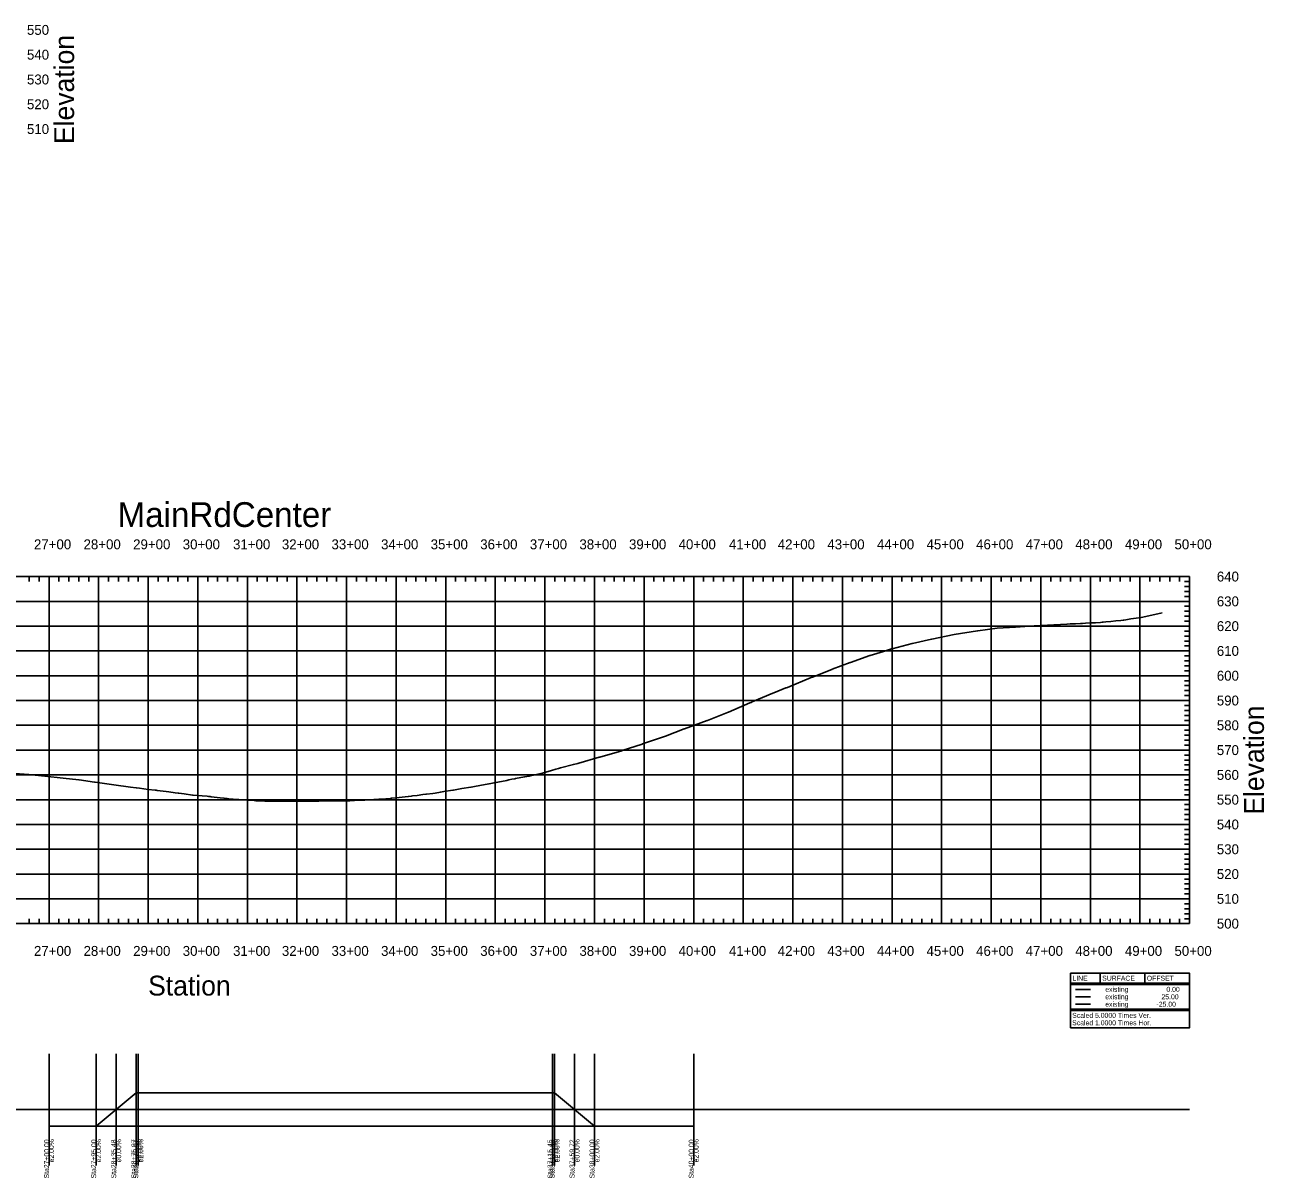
# Model space of a CAD drawing. Extents: x 708167 to 712470, y 374476 to 376945.
# Drawn here: x 709970 to 712470, y 374476 to 376803 of the extents above; entities that cross this region are included whole.
import ezdxf

# ---------------------------------------------------------------- set-up
doc = ezdxf.new("R2010")
doc.units = 0
for name, color, linetype in [('1', 7, 'Continuous'), ('54', 7, 'Continuous'), ('61', 7, 'Continuous'), ('63', 7, 'Continuous'), ('Existing', 7, 'Continuous')]:
    doc.layers.add(name, color=color, linetype=linetype)

msp = doc.modelspace()

# ---------------------------------------------------------------- linework, layer by layer
for points in [[(710019, 374581.2), (710114, 374581.2), (710195, 374648.4), (711038.5, 374648.4), (711119, 374581.2), (711319, 374581.2)], [(708319, 374614.8), (712319, 374614.8)], [(710019, 374581.2), (711319, 374581.2)]]:
    msp.add_lwpolyline(points)
at = {"layer": '54'}
for points in [[(710019, 374727.3), (710019, 374502.3)], [(710114, 374727.3), (710114, 374502.3)], [(710154.5, 374727.3), (710154.5, 374502.3)], [(710195, 374727.3), (710195, 374502.3)], [(710199, 374727.3), (710199, 374502.3)], [(711034.5, 374727.3), (711034.5, 374502.3)], [(711038.5, 374727.3), (711038.5, 374502.3)], [(711078.7, 374727.3), (711078.7, 374502.3)], [(711119, 374727.3), (711119, 374502.3)], [(711319, 374727.3), (711319, 374502.3)]]:
    msp.add_lwpolyline(points, dxfattribs=at)
at = {"layer": '61'}
for p, q in [((708319, 375689.8), (712319, 375689.8)), ((709979, 375689.8), (709979, 375679.8)), ((709999, 375689.8), (709999, 375679.8)), ((710019, 374989.8), (710019, 375689.8)), ((710039, 375689.8), (710039, 375679.8)), ((710059, 375689.8), (710059, 375679.8)), ((710079, 375689.8), (710079, 375679.8)), ((710099, 375689.8), (710099, 375679.8)), ((710119, 374989.8), (710119, 375689.8)), ((710139, 375689.8), (710139, 375679.8)), ((710159, 375689.8), (710159, 375679.8)), ((710179, 375689.8), (710179, 375679.8)), ((710199, 375689.8), (710199, 375679.8)), ((710219, 374989.8), (710219, 375689.8)), ((710239, 375689.8), (710239, 375679.8)), ((710259, 375689.8), (710259, 375679.8)), ((710279, 375689.8), (710279, 375679.8)), ((710299, 375689.8), (710299, 375679.8)), ((710319, 374989.8), (710319, 375689.8)), ((710339, 375689.8), (710339, 375679.8)), ((710359, 375689.8), (710359, 375679.8)), ((710379, 375689.8), (710379, 375679.8)), ((710399, 375689.8), (710399, 375679.8)), ((710419, 374989.8), (710419, 375689.8)), ((710439, 375689.8), (710439, 375679.8)), ((710459, 375689.8), (710459, 375679.8)), ((710479, 375689.8), (710479, 375679.8)), ((710499, 375689.8), (710499, 375679.8)), ((710519, 374989.8), (710519, 375689.8)), ((710539, 375689.8), (710539, 375679.8)), ((710559, 375689.8), (710559, 375679.8)), ((710579, 375689.8), (710579, 375679.8)), ((710599, 375689.8), (710599, 375679.8)), ((710619, 374989.8), (710619, 375689.8)), ((710639, 375689.8), (710639, 375679.8)), ((710659, 375689.8), (710659, 375679.8)), ((710679, 375689.8), (710679, 375679.8)), ((710699, 375689.8), (710699, 375679.8)), ((710719, 374989.8), (710719, 375689.8)), ((710739, 375689.8), (710739, 375679.8)), ((710759, 375689.8), (710759, 375679.8)), ((710779, 375689.8), (710779, 375679.8)), ((710799, 375689.8), (710799, 375679.8)), ((710819, 374989.8), (710819, 375689.8)), ((710839, 375689.8), (710839, 375679.8)), ((710859, 375689.8), (710859, 375679.8)), ((710879, 375689.8), (710879, 375679.8)), ((710899, 375689.8), (710899, 375679.8)), ((710919, 374989.8), (710919, 375689.8)), ((710939, 375689.8), (710939, 375679.8)), ((710959, 375689.8), (710959, 375679.8)), ((710979, 375689.8), (710979, 375679.8)), ((710999, 375689.8), (710999, 375679.8)), ((711019, 374989.8), (711019, 375689.8)), ((711039, 375689.8), (711039, 375679.8)), ((711059, 375689.8), (711059, 375679.8)), ((711079, 375689.8), (711079, 375679.8)), ((711099, 375689.8), (711099, 375679.8)), ((711119, 374989.8), (711119, 375689.8)), ((711139, 375689.8), (711139, 375679.8)), ((711159, 375689.8), (711159, 375679.8)), ((711179, 375689.8), (711179, 375679.8)), ((711199, 375689.8), (711199, 375679.8)), ((711219, 374989.8), (711219, 375689.8)), ((711239, 375689.8), (711239, 375679.8)), ((711259, 375689.8), (711259, 375679.8)), ((711279, 375689.8), (711279, 375679.8)), ((711299, 375689.8), (711299, 375679.8)), ((711319, 374989.8), (711319, 375689.8)), ((711339, 375689.8), (711339, 375679.8)), ((711359, 375689.8), (711359, 375679.8)), ((711379, 375689.8), (711379, 375679.8)), ((711399, 375689.8), (711399, 375679.8)), ((711419, 374989.8), (711419, 375689.8)), ((711439, 375689.8), (711439, 375679.8)), ((711459, 375689.8), (711459, 375679.8)), ((711479, 375689.8), (711479, 375679.8)), ((711499, 375689.8), (711499, 375679.8)), ((711519, 374989.8), (711519, 375689.8)), ((711539, 375689.8), (711539, 375679.8)), ((711559, 375689.8), (711559, 375679.8)), ((711579, 375689.8), (711579, 375679.8)), ((711599, 375689.8), (711599, 375679.8)), ((711619, 374989.8), (711619, 375689.8)), ((711639, 375689.8), (711639, 375679.8)), ((711659, 375689.8), (711659, 375679.8)), ((711679, 375689.8), (711679, 375679.8)), ((711699, 375689.8), (711699, 375679.8)), ((711719, 374989.8), (711719, 375689.8)), ((711739, 375689.8), (711739, 375679.8)), ((711759, 375689.8), (711759, 375679.8)), ((711779, 375689.8), (711779, 375679.8)), ((711799, 375689.8), (711799, 375679.8)), ((711819, 374989.8), (711819, 375689.8)), ((711839, 375689.8), (711839, 375679.8)), ((711859, 375689.8), (711859, 375679.8)), ((711879, 375689.8), (711879, 375679.8)), ((711899, 375689.8), (711899, 375679.8)), ((711919, 374989.8), (711919, 375689.8)), ((711939, 375689.8), (711939, 375679.8)), ((711959, 375689.8), (711959, 375679.8)), ((711979, 375689.8), (711979, 375679.8)), ((711999, 375689.8), (711999, 375679.8)), ((712019, 374989.8), (712019, 375689.8)), ((712039, 375689.8), (712039, 375679.8)), ((712059, 375689.8), (712059, 375679.8)), ((712079, 375689.8), (712079, 375679.8)), ((712099, 375689.8), (712099, 375679.8)), ((712119, 374989.8), (712119, 375689.8)), ((712139, 375689.8), (712139, 375679.8)), ((712159, 375689.8), (712159, 375679.8)), ((712179, 375689.8), (712179, 375679.8)), ((712199, 375689.8), (712199, 375679.8)), ((712219, 374989.8), (712219, 375689.8)), ((712239, 375689.8), (712239, 375679.8)), ((712259, 375689.8), (712259, 375679.8)), ((712279, 375689.8), (712279, 375679.8)), ((712299, 375689.8), (712299, 375679.8)), ((712319, 375679.8), (712309, 375679.8)), ((712319, 375669.8), (712309, 375669.8)), ((712319, 374989.8), (712319, 375689.8)), ((712319, 375659.8), (712309, 375659.8)), ((712319, 375649.8), (712309, 375649.8)), ((708319, 375639.8), (712319, 375639.8)), ((712319, 375629.8), (712309, 375629.8)), ((712319, 375619.8), (712309, 375619.8)), ((712319, 375609.8), (712309, 375609.8)), ((712319, 375599.8), (712309, 375599.8)), ((708319, 375589.8), (712319, 375589.8)), ((712319, 375579.8), (712309, 375579.8)), ((712319, 375569.8), (712309, 375569.8)), ((712319, 375559.8), (712309, 375559.8)), ((712319, 375549.8), (712309, 375549.8)), ((708319, 375539.8), (712319, 375539.8)), ((712319, 375529.8), (712309, 375529.8)), ((712319, 375519.8), (712309, 375519.8)), ((712319, 375509.8), (712309, 375509.8)), ((712319, 375499.8), (712309, 375499.8)), ((708319, 375489.8), (712319, 375489.8)), ((712319, 375479.8), (712309, 375479.8)), ((712319, 375469.8), (712309, 375469.8)), ((712319, 375459.8), (712309, 375459.8)), ((712319, 375449.8), (712309, 375449.8)), ((708319, 375439.8), (712319, 375439.8)), ((712319, 375429.8), (712309, 375429.8)), ((712319, 375419.8), (712309, 375419.8)), ((712319, 375409.8), (712309, 375409.8)), ((712319, 375399.8), (712309, 375399.8)), ((708319, 375389.8), (712319, 375389.8)), ((712319, 375379.8), (712309, 375379.8)), ((712319, 375369.8), (712309, 375369.8)), ((712319, 375359.8), (712309, 375359.8)), ((712319, 375349.8), (712309, 375349.8)), ((708319, 375339.8), (712319, 375339.8)), ((712319, 375329.8), (712309, 375329.8)), ((712319, 375319.8), (712309, 375319.8)), ((712319, 375309.8), (712309, 375309.8)), ((712319, 375299.8), (712309, 375299.8)), ((708319, 375289.8), (712319, 375289.8)), ((712319, 375279.8), (712309, 375279.8)), ((712319, 375269.8), (712309, 375269.8)), ((712319, 375259.8), (712309, 375259.8)), ((712319, 375249.8), (712309, 375249.8)), ((708319, 375239.8), (712319, 375239.8)), ((712319, 375229.8), (712309, 375229.8)), ((712319, 375219.8), (712309, 375219.8)), ((712319, 375209.8), (712309, 375209.8)), ((712319, 375199.8), (712309, 375199.8)), ((708319, 375189.8), (712319, 375189.8)), ((712319, 375179.8), (712309, 375179.8)), ((712319, 375169.8), (712309, 375169.8)), ((712319, 375159.8), (712309, 375159.8)), ((712319, 375149.8), (712309, 375149.8)), ((708319, 375139.8), (712319, 375139.8)), ((712319, 375129.8), (712309, 375129.8)), ((712319, 375119.8), (712309, 375119.8)), ((712319, 375109.8), (712309, 375109.8)), ((712319, 375099.8), (712309, 375099.8)), ((708319, 375089.8), (712319, 375089.8)), ((712319, 375079.8), (712309, 375079.8)), ((712319, 375069.8), (712309, 375069.8)), ((712319, 375059.8), (712309, 375059.8)), ((712319, 375049.8), (712309, 375049.8)), ((708319, 375039.8), (712319, 375039.8)), ((712319, 375029.8), (712309, 375029.8)), ((712319, 375019.8), (712309, 375019.8)), ((709979, 374989.8), (709979, 374999.8)), ((709999, 374989.8), (709999, 374999.8)), ((710039, 374989.8), (710039, 374999.8)), ((710059, 374989.8), (710059, 374999.8)), ((710079, 374989.8), (710079, 374999.8)), ((710099, 374989.8), (710099, 374999.8)), ((710139, 374989.8), (710139, 374999.8)), ((710159, 374989.8), (710159, 374999.8)), ((710179, 374989.8), (710179, 374999.8)), ((710199, 374989.8), (710199, 374999.8)), ((710239, 374989.8), (710239, 374999.8)), ((710259, 374989.8), (710259, 374999.8)), ((710279, 374989.8), (710279, 374999.8)), ((710299, 374989.8), (710299, 374999.8)), ((710339, 374989.8), (710339, 374999.8)), ((710359, 374989.8), (710359, 374999.8)), ((710379, 374989.8), (710379, 374999.8)), ((710399, 374989.8), (710399, 374999.8)), ((710439, 374989.8), (710439, 374999.8)), ((710459, 374989.8), (710459, 374999.8)), ((710479, 374989.8), (710479, 374999.8)), ((710499, 374989.8), (710499, 374999.8)), ((710539, 374989.8), (710539, 374999.8)), ((710559, 374989.8), (710559, 374999.8)), ((710579, 374989.8), (710579, 374999.8)), ((710599, 374989.8), (710599, 374999.8)), ((710639, 374989.8), (710639, 374999.8)), ((710659, 374989.8), (710659, 374999.8)), ((710679, 374989.8), (710679, 374999.8)), ((710699, 374989.8), (710699, 374999.8)), ((710739, 374989.8), (710739, 374999.8)), ((710759, 374989.8), (710759, 374999.8)), ((710779, 374989.8), (710779, 374999.8)), ((710799, 374989.8), (710799, 374999.8)), ((710839, 374989.8), (710839, 374999.8)), ((710859, 374989.8), (710859, 374999.8)), ((710879, 374989.8), (710879, 374999.8)), ((710899, 374989.8), (710899, 374999.8)), ((710939, 374989.8), (710939, 374999.8)), ((710959, 374989.8), (710959, 374999.8)), ((710979, 374989.8), (710979, 374999.8)), ((710999, 374989.8), (710999, 374999.8)), ((711039, 374989.8), (711039, 374999.8)), ((711059, 374989.8), (711059, 374999.8)), ((711079, 374989.8), (711079, 374999.8)), ((711099, 374989.8), (711099, 374999.8)), ((711139, 374989.8), (711139, 374999.8)), ((711159, 374989.8), (711159, 374999.8)), ((711179, 374989.8), (711179, 374999.8)), ((711199, 374989.8), (711199, 374999.8)), ((711239, 374989.8), (711239, 374999.8)), ((711259, 374989.8), (711259, 374999.8)), ((711279, 374989.8), (711279, 374999.8)), ((711299, 374989.8), (711299, 374999.8)), ((711339, 374989.8), (711339, 374999.8)), ((711359, 374989.8), (711359, 374999.8)), ((711379, 374989.8), (711379, 374999.8)), ((711399, 374989.8), (711399, 374999.8)), ((711439, 374989.8), (711439, 374999.8)), ((711459, 374989.8), (711459, 374999.8)), ((711479, 374989.8), (711479, 374999.8)), ((711499, 374989.8), (711499, 374999.8)), ((711539, 374989.8), (711539, 374999.8)), ((711559, 374989.8), (711559, 374999.8)), ((711579, 374989.8), (711579, 374999.8)), ((711599, 374989.8), (711599, 374999.8)), ((711639, 374989.8), (711639, 374999.8)), ((711659, 374989.8), (711659, 374999.8)), ((711679, 374989.8), (711679, 374999.8)), ((711699, 374989.8), (711699, 374999.8)), ((711739, 374989.8), (711739, 374999.8)), ((711759, 374989.8), (711759, 374999.8)), ((711779, 374989.8), (711779, 374999.8)), ((711799, 374989.8), (711799, 374999.8)), ((711839, 374989.8), (711839, 374999.8)), ((711859, 374989.8), (711859, 374999.8)), ((711879, 374989.8), (711879, 374999.8)), ((711899, 374989.8), (711899, 374999.8)), ((711939, 374989.8), (711939, 374999.8)), ((711959, 374989.8), (711959, 374999.8)), ((711979, 374989.8), (711979, 374999.8)), ((711999, 374989.8), (711999, 374999.8)), ((712039, 374989.8), (712039, 374999.8)), ((712059, 374989.8), (712059, 374999.8)), ((712079, 374989.8), (712079, 374999.8)), ((712099, 374989.8), (712099, 374999.8)), ((712139, 374989.8), (712139, 374999.8)), ((712159, 374989.8), (712159, 374999.8)), ((712179, 374989.8), (712179, 374999.8)), ((712199, 374989.8), (712199, 374999.8)), ((712239, 374989.8), (712239, 374999.8)), ((712259, 374989.8), (712259, 374999.8)), ((712279, 374989.8), (712279, 374999.8)), ((712299, 374989.8), (712299, 374999.8)), ((712319, 375009.8), (712309, 375009.8)), ((712319, 374999.8), (712309, 374999.8)), ((708319, 374989.8), (712319, 374989.8)), ((712079, 374869.8), (712319, 374869.8)), ((712139, 374889.8), (712139, 374869.8)), ((712229, 374889.8), (712229, 374869.8)), ((712079, 374867.3), (712319, 374867.3)), ((712079, 374817.3), (712319, 374817.3)), ((712079, 374814.8), (712319, 374814.8))]:
    msp.add_line(p, q, dxfattribs=at)
msp.add_lwpolyline([(712079, 374889.8), (712319, 374889.8), (712319, 374779.8), (712079, 374779.8)], close=True, dxfattribs=at)
at = {"layer": '63'}
for p, q in [((712089, 374842.3), (712119, 374842.3)), ((712089, 374827.3), (712119, 374827.3))]:
    msp.add_line(p, q, dxfattribs=at)
at = {"layer": 'Existing'}
msp.add_line((712089, 374857.3), (712119, 374857.3), dxfattribs=at)
msp.add_lwpolyline([(709941.7, 375293.2), (709977.7, 375290.3), (709978.4, 375290.3), (710010.5, 375287.5), (710010.8, 375287.4), (710047.4, 375283.3), (710047.5, 375283.3), (710079.1, 375279.5), (710079.5, 375279.5), (710111, 375275.3), (710112, 375275.2), (710149.4, 375269.9), (710149.5, 375269.9), (710149.6, 375269.9), (710183.1, 375265.3), (710194.5, 375263.8), (710195.3, 375263.7), (710201.2, 375262.9), (710219.2, 375260.6), (710233, 375258.9), (710233.5, 375258.8), (710234, 375258.8), (710235, 375258.7), (710237.3, 375258.4), (710255.4, 375256.1), (710260.9, 375255.4), (710273.4, 375253.7), (710279.4, 375253), (710280.4, 375252.8), (710280.5, 375253), (710280.9, 375252.9), (710291.5, 375251.5), (710308.6, 375249.2), (710309.6, 375249.1), (710309.8, 375249.1), (710327.6, 375247.5), (710338.1, 375246.6), (710340.3, 375246.4), (710340.4, 375246.4), (710344.2, 375245.9), (710345.7, 375245.8), (710363.8, 375243.7), (710371.6, 375242.8), (710372.1, 375242.8), (710378.5, 375242.2), (710381.8, 375241.8), (710399.9, 375240), (710401.2, 375239.9), (710402.4, 375239.8), (710418, 375238.9), (710432.4, 375238), (710432.7, 375238), (710436, 375237.8), (710454.1, 375237), (710462.3, 375236.7), (710463.2, 375236.6), (710472.2, 375236.6), (710490.2, 375236.6), (710496.4, 375236.6), (710497.6, 375236.6), (710508.3, 375236.7), (710526.4, 375236.8), (710528.9, 375236.9), (710530.1, 375236.9), (710544.4, 375236.9), (710562.1, 375237), (710562.5, 375237), (710562.9, 375237), (710580.6, 375237.2), (710590.2, 375237.3), (710590.8, 375237.3), (710598.6, 375237.4), (710616.7, 375237.4), (710622.2, 375237.5), (710624, 375237.5), (710625.8, 375237.6), (710634.8, 375238), (710652.8, 375238.8), (710655.7, 375238.9), (710655.9, 375239), (710670.9, 375239.8), (710674, 375239.9), (710678.6, 375240.3), (710680.9, 375240.4), (710683.8, 375240.6), (710689, 375241), (710707.1, 375242.5), (710707.8, 375242.5), (710709.4, 375242.6), (710725.1, 375244.3), (710743.2, 375246.3), (710744.2, 375246.5), (710749.6, 375246.8), (710751.8, 375247.3), (710761.3, 375248.2), (710761.4, 375248.2), (710772.8, 375250.1), (710779, 375250.6), (710779.3, 375250.7), (710780.5, 375251), (710793.1, 375252.2), (710797.4, 375252.9), (710798, 375253), (710808.3, 375255.1), (710815.5, 375256.1), (710833.5, 375258.9), (710834.7, 375259), (710838.3, 375259.7), (710844.9, 375260.9), (710851.6, 375262.1), (710869.7, 375265.1), (710870, 375265.2), (710870.3, 375265.2), (710876.7, 375266.3), (710887.7, 375268.3), (710905.8, 375271.6), (710906.8, 375271.8), (710913, 375273), (710916.2, 375273.6), (710916.3, 375273.7), (710917.1, 375274), (710923.9, 375275.3), (710941.9, 375278.8), (710946.3, 375279.7), (710952, 375280.9), (710958, 375282), (710958.6, 375282), (710960, 375282.3), (710978.1, 375285.7), (710987, 375287.5), (710993.8, 375289), (710996.1, 375289.3), (710998.5, 375289.7), (711014.2, 375293.4), (711018.1, 375294.3), (711018.7, 375294.3), (711019.3, 375294.4), (711020.6, 375295), (711032.3, 375298.8), (711041.2, 375301.6), (711046.1, 375302.9), (711050.3, 375304), (711076.5, 375310.8), (711085.1, 375313), (711087.2, 375313.6), (711128.4, 375325.3), (711129, 375325.5), (711129, 375325.5), (711129.7, 375325.7), (711173.9, 375338.6), (711174.5, 375338.8), (711175, 375339), (711215, 375351.8), (711215.1, 375351.8), (711215.9, 375352.1), (711262, 375368.2), (711300, 375382.6), (711300.6, 375382.8), (711346, 375399.6), (711346.3, 375399.7), (711346.6, 375399.8), (711387.3, 375415.8), (711389, 375416.5), (711432.5, 375435), (711434.9, 375436), (711437.1, 375437.1), (711478.4, 375454.3), (711480.7, 375455.3), (711504.8, 375465.3), (711505.2, 375465.5), (711505.6, 375465.1), (711508.5, 375466.3), (711556, 375485.9), (711558.6, 375486.9), (711597.7, 375502.3), (711598.6, 375502.7), (711634.9, 375516.6), (711634.9, 375516.6), (711635, 375516.6), (711635, 375516.7), (711635.2, 375516.7), (711635.4, 375516.8), (711635.4, 375516.8), (711635.4, 375516.8), (711635.4, 375516.8), (711674.4, 375530.6), (711674.8, 375530.7), (711675, 375530.8), (711701.7, 375538.9), (711718.2, 375543.9), (711718.6, 375544), (711719, 375544.1), (711759.8, 375554.5), (711760.3, 375554.7), (711798.6, 375563.3), (711799.1, 375563.4), (711844.4, 375572.9), (711891.1, 375580.5), (711891.5, 375580.6), (711891.9, 375580.6), (711930.8, 375585.6), (711930.9, 375585.6), (711967.9, 375587.8), (711968.2, 375587.8), (712005.7, 375590.1), (712006.5, 375590.1), (712006.6, 375590.1), (712045.1, 375592.3), (712045.6, 375592.5), (712045.6, 375592.5), (712071.9, 375593.8), (712071.9, 375593.8), (712071.9, 375593.8), (712078.5, 375594.2), (712088.7, 375594.7), (712098.9, 375595.2), (712101.9, 375595.4), (712102, 375595.4), (712103, 375595.4), (712109.1, 375595.7), (712119.3, 375596.3), (712129.5, 375596.8), (712139.7, 375597.4), (712143, 375597.6), (712144.5, 375597.7), (712149.9, 375598.2), (712160.1, 375599.3), (712170.3, 375600.3), (712180.5, 375601.4), (712185.4, 375601.9), (712186.7, 375602), (712190.7, 375602.7), (712200.9, 375604.3), (712211.1, 375605.9), (712221.3, 375607.4), (712224.9, 375608), (712263.9, 375616.8)], dxfattribs=at)

# ---------------------------------------------------------------- texts
at = {"layer": '1'}
for s, height, p in [('MainRdCenter', 50, (710157.2, 375789.8)), ('Station', 40, (710218.8, 374844.8)), (' LINE ', 10, (712079, 374874.8)), (' SURFACE ', 10, (712139, 374874.8)), (' OFFSET ', 10, (712229, 374874.8)), ('existing', 10, (712149, 374852.3)), ('existing', 10, (712149, 374837.3)), ('25.00', 10, (712262.4, 374837.3)), ('0.00', 10, (712272.4, 374852.3)), ('existing', 10, (712149, 374822.3)), ('-25.00', 10, (712252.4, 374822.3)), ('Scaled 5.0000 Times Ver.', 10, (712082.4, 374799.8)), ('Scaled 1.0000 Times Hor.', 10, (712082.4, 374784.8))]:
    msp.add_text(s, height=height, dxfattribs=at).set_placement(p)
at = {"layer": '54'}
for s, p in [('Sta27+00.00', (710019, 374475.9)), ('e2.00%', (710029, 374508.3)), ('Sta27+95.00', (710114, 374475.9)), ('e2.00%', (710124, 374508.3)), ('Sta28+35.48', (710154.5, 374475.8)), ('e0.00%', (710164.5, 374508.3)), ('Sta28+75.97', (710194.9, 374475.9)), ('Sta28+79.97', (710198.9, 374475.9)), ('e2.00%', (710205, 374508.3)), ('e2.00%', (710209, 374508.3)), ('Sta37+15.45', (711034.4, 374475.8)), ('Sta37+19.45', (711038.4, 374475.8)), ('e2.00%', (711044.5, 374508.3)), ('e2.00%', (711048.5, 374508.3)), ('Sta37+59.72', (711078.7, 374476)), ('e0.00%', (711088.8, 374508.3)), ('Sta38+00.00', (711119, 374475.9)), ('e2.00%', (711129, 374508.3)), ('Sta40+00.00', (711319, 374475.9)), ('e2.00%', (711329, 374508.3))]:
    msp.add_text(s, height=10, rotation=90, dxfattribs=at).set_placement(p)
at = {"layer": '61'}
for s, p in [('550', (709974.5, 376782.3)), ('550', (709974.5, 376782.3)), ('540', (709974.5, 376732.3)), ('530', (709974.5, 376682.3)), ('520', (709974.5, 376632.3)), ('510', (709974.5, 376582.3)), ('27+00', (709988.6, 375744.8)), ('28+00', (710088.6, 375744.8)), ('29+00', (710188.6, 375744.8)), ('30+00', (710288.6, 375744.8)), ('31+00', (710390.1, 375744.8)), ('32+00', (710488.6, 375744.8)), ('33+00', (710588.6, 375744.8)), ('34+00', (710688.6, 375744.8)), ('35+00', (710788.6, 375744.8)), ('36+00', (710888.6, 375744.8)), ('37+00', (710988.6, 375744.8)), ('38+00', (711088.6, 375744.8)), ('39+00', (711188.6, 375744.8)), ('40+00', (711288.6, 375744.8)), ('41+00', (711390.1, 375744.8)), ('42+00', (711488.6, 375744.8)), ('43+00', (711588.6, 375744.8)), ('44+00', (711688.6, 375744.8)), ('45+00', (711788.6, 375744.8)), ('46+00', (711888.6, 375744.8)), ('47+00', (711988.6, 375744.8)), ('48+00', (712088.6, 375744.8)), ('49+00', (712188.6, 375744.8)), ('50+00', (712288.6, 375744.8)), ('640', (712374, 375679.8)), ('640', (712374, 375679.8)), ('630', (712374, 375629.8)), ('620', (712374, 375579.8)), ('610', (712374, 375529.8)), ('600', (712374, 375479.8)), ('590', (712374, 375429.8)), ('580', (712374, 375379.8)), ('570', (712374, 375329.8)), ('560', (712374, 375279.8)), ('550', (712374, 375229.8)), ('540', (712374, 375179.8)), ('530', (712374, 375129.8)), ('520', (712374, 375079.8)), ('510', (712374, 375029.8)), ('500', (712374, 374979.8)), ('27+00', (709988.6, 374924.8)), ('28+00', (710088.6, 374924.8)), ('29+00', (710188.6, 374924.8)), ('30+00', (710288.6, 374924.8)), ('31+00', (710390.1, 374924.8)), ('32+00', (710488.6, 374924.8)), ('33+00', (710588.6, 374924.8)), ('34+00', (710688.6, 374924.8)), ('35+00', (710788.6, 374924.8)), ('36+00', (710888.6, 374924.8)), ('37+00', (710988.6, 374924.8)), ('38+00', (711088.6, 374924.8)), ('39+00', (711188.6, 374924.8)), ('40+00', (711288.6, 374924.8)), ('41+00', (711390.1, 374924.8)), ('42+00', (711488.6, 374924.8)), ('43+00', (711588.6, 374924.8)), ('44+00', (711688.6, 374924.8)), ('45+00', (711788.6, 374924.8)), ('46+00', (711888.6, 374924.8)), ('47+00', (711988.6, 374924.8)), ('48+00', (712088.6, 374924.8)), ('49+00', (712188.6, 374924.8)), ('50+00', (712288.6, 374924.8))]:
    msp.add_text(s, height=20, dxfattribs=at).set_placement(p)
for p in [(710069.5, 376562.1), (712469, 375209.6)]:
    msp.add_text('Elevation', height=40, rotation=90, dxfattribs=at).set_placement(p)

doc.saveas('drawing.dxf')
